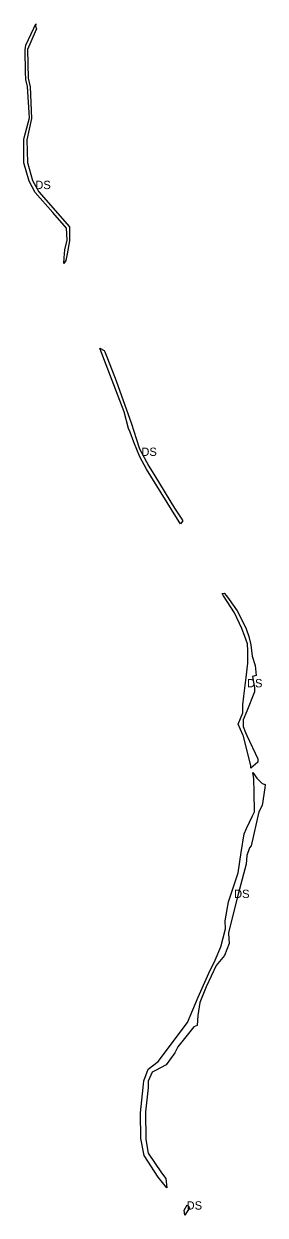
# Model space of a CAD drawing. Extents: x -477403 to -475386, y -1156331 to -1149624.
# Drawn here: x -476535 to -476245, y -1154402 to -1152970 of the extents above; entities that cross this region are included whole.
import ezdxf

# ---------------------------------------------------------------- set-up
doc = ezdxf.new("R2010")
doc.units = 0
doc.layers.add('4', color=7, linetype='Continuous')

msp = doc.modelspace()

# ---------------------------------------------------------------- linework, layer by layer
at = {"layer": '4'}
for points in [[(-476519.781, -1152976.361), (-476521.36, -1152980.06), (-476530.4, -1153001.24), (-476529.61, -1153035.55), (-476527.31, -1153046.26), (-476525.58, -1153084.03), (-476531.41, -1153109.71), (-476530.4, -1153136.97), (-476524.65, -1153158.76), (-476516.95, -1153172.14), (-476480.08, -1153214.48), (-476480.05, -1153231.19), (-476482.96, -1153246.73), (-476484.497, -1153254.938), (-476486.972, -1153258.443), (-476486.44, -1153251.42), (-476485.73, -1153242.05), (-476482.86, -1153230.19), (-476483.22, -1153222.89), (-476483.58, -1153215.73), (-476499.999, -1153197.158), (-476521.48, -1153172.86), (-476528.39, -1153159.55), (-476534.86, -1153137.4), (-476534.93, -1153109.56), (-476534.55, -1153107.24), (-476528.3, -1153083.22), (-476530.38, -1153045.6), (-476532.68, -1153037.11), (-476532.819, -1153028.609), (-476533.26, -1153001.58), (-476532.32, -1152996.04), (-476522.98, -1152975.49), (-476520.669, -1152970.407), (-476520.8, -1152973.09)], [(-476438.294, -1153362.937), (-476437.71, -1153364.35), (-476434.42, -1153372.31), (-476424.07, -1153399.43), (-476405.65, -1153450.93), (-476399.9, -1153468.77), (-476396.01, -1153480.92), (-476384.72, -1153501.85), (-476377.53, -1153513.29), (-476353.72, -1153552.2), (-476346.01, -1153564.26), (-476343.94, -1153567.497), (-476346.698, -1153571.147), (-476348.27, -1153568.62), (-476357.34, -1153554.04), (-476387.53, -1153505.52), (-476395.58, -1153490.78), (-476402.77, -1153472.87), (-476406.94, -1153460.93), (-476409.06, -1153456.76), (-476414.52, -1153436.69), (-476443.18, -1153361.18), (-476443.62, -1153360.021)], [(-476291.29, -1153657.6), (-476288.17, -1153662.07), (-476278.75, -1153675.54), (-476272.64, -1153687.27), (-476267.82, -1153697.27), (-476264.37, -1153706.47), (-476262.03, -1153716.56), (-476260.5, -1153730.17), (-476256.97, -1153741.51), (-476255.69, -1153753.31), (-476260.07, -1153754.39), (-476257.82, -1153768.04), (-476257.89, -1153772.79), (-476267.1, -1153796.02), (-476271.34, -1153806.45), (-476271.5, -1153810.08), (-476271.16, -1153814.53), (-476268.66, -1153821.92), (-476267, -1153825.42), (-476253.61, -1153853.66), (-476253.66, -1153857.49), (-476262.22, -1153864.64), (-476262.17, -1153862.03), (-476270.91, -1153826.31), (-476271.92, -1153824.79), (-476277.31, -1153811.78), (-476271.63, -1153798.33), (-476271.77, -1153788.47), (-476270.55, -1153778.1), (-476267.93, -1153755.92), (-476265.77, -1153738.37), (-476265.77, -1153723.7), (-476266.2, -1153715.5), (-476269.71, -1153705.42), (-476272.63, -1153698.17), (-476273.08, -1153696.83), (-476281.7, -1153677.92), (-476294.93, -1153657.5), (-476296.772, -1153654.657), (-476294.12, -1153654.5)], [(-476244.894, -1153884.447), (-476245.47, -1153888.43), (-476248.54, -1153909.67), (-476252.71, -1153917.15), (-476261.8, -1153957.79), (-476263.56, -1153960.31), (-476267.08, -1153969.59), (-476267.87, -1153979.87), (-476277.31, -1154016.12), (-476289.04, -1154062.23), (-476288.95, -1154063.5), (-476288.13, -1154075.32), (-476293.62, -1154089.64), (-476303.64, -1154101.58), (-476315.79, -1154127.25), (-476323.56, -1154146.24), (-476325.79, -1154162), (-476326.7, -1154173.85), (-476330.45, -1154175.59), (-476349.66, -1154199.4), (-476353.32, -1154206.52), (-476363.9, -1154221.26), (-476376.88, -1154227.95), (-476380.8, -1154229.97), (-476385.55, -1154240.54), (-476385.62, -1154248.88), (-476388.55, -1154277.39), (-476388.51, -1154311.01), (-476385.42, -1154327.09), (-476369.56, -1154350.97), (-476364.31, -1154357.48), (-476363.09, -1154369.01), (-476373.35, -1154356.06), (-476390.47, -1154330.16), (-476394.49, -1154309.59), (-476394.78, -1154278.66), (-476391.68, -1154248.45), (-476390.53, -1154240.18), (-476385.64, -1154226.37), (-476373.48, -1154217.09), (-476338.31, -1154170.41), (-476325.29, -1154139.98), (-476312.49, -1154110.93), (-476305.15, -1154095.17), (-476298.28, -1154079.46), (-476292.53, -1154057.59), (-476292.96, -1154048.24), (-476288.93, -1154025.22), (-476277.42, -1153990.41), (-476273.72, -1153965.9), (-476270.34, -1153943.55), (-476267.264, -1153937), (-476260.27, -1153922.11), (-476257.75, -1153917.22), (-476258.211, -1153893.51), (-476258.52, -1153877.66), (-476259.84, -1153869.71), (-476254.8, -1153876.71), (-476248.56, -1153883.09)], [(-476335.81, -1154392.99), (-476341.495, -1154401.726), (-476342.187, -1154395.723), (-476338.54, -1154389.36)]]:
    msp.add_lwpolyline(points, close=True, dxfattribs=at)

# ---------------------------------------------------------------- texts
for p in [(-476521.124, -1153168.946), (-476393.694, -1153489.559), (-476266.791, -1153767.569), (-476282.28, -1154020.676), (-476339.319, -1154395.025)]:
    msp.add_text('DS', height=10, dxfattribs=at).set_placement(p)

doc.saveas('drawing.dxf')
